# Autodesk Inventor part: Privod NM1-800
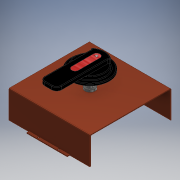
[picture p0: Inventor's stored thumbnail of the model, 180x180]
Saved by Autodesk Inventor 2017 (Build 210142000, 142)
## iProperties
Part Number: Privod NM1-800
Material: Типовые
Document SubType Name: Modeling
Designer: RSagdiev
Density: 1 g/cm^3
Appearance: По умолчанию
Author: RSagdiev
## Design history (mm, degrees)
sketch "Эскиз1"
  geometry: L1 (-52.5, 111.5)-(52.5, 111.5); L2 (52.5, 111.5)-(52.5, 103); L3 (52.5, 103)-(28.25, 103); L4 (-52.5, 103)-(-52.5, 111.5); L5 (0, 0)-(119.698, 0); L6 (0, 0)-(-104.809, 0); L7 (0, 94.88)-(0, -60.954); L8 (-28.25, 103)-(-24.25, 103); L9 (-24.25, 103)-(-24.25, 108); L10 (-26.25, 110)-(-26.25, 110); L11 (-28.25, 108)-(-28.25, 103); L12 (24.25, 103)-(24.25, 108); L13 (26.25, 110)-(26.25, 110); L14 (28.25, 103)-(24.25, 103); L15 (28.25, 108)-(28.25, 103); L16 (-28.25, 103)-(-52.5, 103); L17 (-24.25, 103)-(-28.25, 103); L18 (24.25, 103)-(-24.25, 103); L19 (28.25, 103)-(24.25, 103); A1 r 2 centre (-26.25, 108) between (-26.25, 110) and (-28.25, 108); A2 r 2 centre (-26.25, 108) between (-24.25, 108) and (-26.25, 110); A3 r 2 centre (26.25, 108) between (26.25, 110) and (24.25, 108); A4 r 2 centre (26.25, 108) between (28.25, 108) and (26.25, 110); 5 further points
  constraints: 38 end point, 10 point on line, 10 symmetric about line, 8 parallel, 8 point on circle, 4 centre point, 4 horizontal, 4 tangent, 2 perpendicular, 1 concentric, 1 midpoint, 1 vertical, 2 other
  dimensions: "d0" = 103 distance between parallel lines of L3 L6 (= 0.5 x Высота); "d1" = 8.5 distance of L1.end L2.end; "d2" = 105 distance between parallel lines of L2 L4 (= 0.5 x Ширина); "d3" = 4 distance of point (-28.25, 110) point (-24.25, 110); "d4" = 7 distance of point (-24.25, 110) L8.end; "d5" = 2 radius of A1 (derived); "d6" = 26.25 distance from line of L4 A1.centre (= 0.25 x d2)
extrude "Выдавливание1" new body sketch "Эскиз1" distance "d7" = 2; taper "d8" = 0 deg
mirror "Зеркальное отражение1"
sketch "Эскиз2"
  geometry: L1 (-52.5, 111.5)-(-52.5, 103) reference; L2 (52.5, 103)-(52.5, 111.5) reference; L3 (-52.5, -111.5)-(-52.5, -103) reference; L4 (52.5, -103)-(52.5, -111.5) reference; L5 (-105, 105)-(105, 105); L6 (105, 105)-(105, 103); L7 (105, 103)-(-105, 103); L8 (-105, 103)-(-105, 105); L9 (-52.5, 103)-(-28.25, 103) reference
  constraints: 8 end point, 2 parallel, 1 collinear, 1 horizontal, 1 perpendicular
  dimensions: "d13" = 210 distance of L5.start L5.end (= Ширина); "d14" = 2 distance of L5.end L6.end; "d15" = 52.5 distance between parallel lines of L1 L8 (= 0.25 x d13)
extrude "Выдавливание2" join sketch "Эскиз2" distance "d11" = 72 (computed from H1); taper "d12" = 0 deg
mirror "Зеркальное отражение2"
sketch "Эскиз3"
  geometry: L1 (-105, 105)-(-52.5, 105) reference; L2 (105, -105)-(-105, -105) reference; L3 (-105, 105)-(105, 105); L4 (105, 105)-(105, -105); L5 (105, -105)-(-105, -105); L6 (-105, -105)-(-105, 105); 1 further point
  constraints: 8 end point, 2 parallel, 1 horizontal, 1 perpendicular
extrude "Выдавливание3" join sketch "Эскиз3" distance "d16" = 2; taper "d17" = 0 deg
fillet "Сопряжение1" dims "d18" = 2
sketch "Эскиз4"
  geometry: L1 (105, -101)-(-105, -101) reference; L2 (105, -101)-(105, 101) reference; L3 (-105, 101)-(105, 101) reference; L4 (-105, 101)-(-105, -101) reference; L5 (-105, 101)-(-105, -101) reference; L6 (-105, -101)-(105, 101); L7 (105, -101)-(105, 101) reference; L8 (-105, 101)-(105, -101); C1 r 5 at (0, 0); 1 further point
  constraints: 4 end point, 1 centre point, 1 coincident
  dimensions: "d19" = 10 diameter of C1
extrude "Выдавливание4" cut sketch "Эскиз4" distance "d20" = 10; taper "d21" = 0 deg
sketch "Эскиз5"
  geometry: C1 r 5 at (0, 0) reference; C2 r 5 at (0, 0); C3 r 8 at (0, 0); 1 further point
  constraints: 2 centre point, 2 coincident
  dimensions: "d22" = 16 diameter of C3
extrude "Выдавливание5" new body sketch "Эскиз5" distance "d23" = 25.33333 (= 0.333333 x H1); taper "d24" = 0 deg
sketch "Эскиз6"
  geometry: C1 r 5 at (0, 0) reference; C2 r 5 at (0, 0); 1 further point
  constraints: 1 centre point, 1 coincident
extrude "Выдавливание6" new body sketch "Эскиз6" distance "d25" = 75.33333 (computed from H1); taper "d26" = 0 deg
sketch "Эскиз7"
  geometry: C1 r 5 at (0, 0) reference; C2 r 13 at (0, 0); C3 r 8 at (0, 0); C4 r 5 at (0, 0); 1 further point
  constraints: 3 centre point, 3 coincident
  dimensions: "d27" = 26 diameter of C2; "d28" = 16 diameter of C3; "d29" = 10 diameter of C4
extrude "Выдавливание7" new body sketch "Эскиз7" distance "d30" = 5; taper "d31" = 0 deg
extrude "Выдавливание8" join sketch "Эскиз7" distance "d32" = 20; taper "d33" = 0 deg
sketch "Эскиз8"
  geometry: C1 r 7 at (0, 0); 1 further point
  constraints: 1 centre point, 1 coincident
  dimensions: "d34" = 14 diameter of C1
extrude "Выдавливание9" new body sketch "Эскиз8" distance "d35" = 3; taper "d36" = 0 deg
fillet "Сопряжение2" dims "d37" = 3
sketch "Эскиз9"
  geometry: L1 (1, 13.17)-(-1, 13.17); L2 (-1, 13.17)-(-1, -13.17); L3 (-1, -13.17)-(1, -13.17); L4 (1, -13.17)-(1, 13.17); L5 (1, 13.17)-(-1, -13.17); L6 (-1, 13.17)-(1, -13.17); L7 (17.109, -1)-(-17.109, -1); L8 (-17.109, -1)-(-17.109, 1); L9 (-17.109, 1)-(17.109, 1); L10 (17.109, 1)-(17.109, -1); L11 (17.109, -1)-(-17.109, 1); L12 (-17.109, -1)-(17.109, 1); C1 r 4 at (0, 0) reference; C2 r 5 at (0, 0) reference; 1 further point
  constraints: 24 end point, 4 midpoint, 4 parallel, 2 horizontal, 2 perpendicular
  dimensions: "d38" = 2 distance of L3.end L2.end; "d39" = 2 distance of L7.end L8.end
extrude "Выдавливание10" cut sketch "Эскиз9" distance "d40" = 1; taper "d41" = 0 deg
sketch "Эскиз10"
  geometry: C1 r 17.5 at (0, 0); A1 r 4 centre (0, 0) between (1, -3.873) and (3.873, -1) reference; 1 further point
  constraints: 1 centre point, 1 coincident
  dimensions: "d42" = 35 diameter of C1
extrude "Выдавливание11" new body sketch "Эскиз10" distance "d43" = 6; taper "d44" = 0 deg; dims "d48" = 3, "d49" = 0
sketch "Эскиз11"
  geometry: C1 r 7 at (0, 0); C2 r 22.5 at (0, 0); 1 further point
  constraints: 2 centre point, 1 coincident
  dimensions: "d45" = 45 diameter of C2
extrude "Выдавливание12" join sketch "Эскиз11" distance "d46" = 6; taper "d47" = 0 deg
sketch "Эскиз12"
  geometry: L1 (-4, -49.361)-(4, -49.361); L2 (10, -43.361)-(10, 10.738); L3 (-10, 10.738)-(-10, -43.361); L4 (-10, -49.361)-(10, 14.361); L5 (10, -49.361)-(-10, 14.361); L6 (-12, 12.738)-(12, 12.738); A1 r 17.5 centre (0, 0) between (10, 14.361) and (0, -17.5) reference; A2 r 17.5 centre (0, 0) between (10, 14.361) and (0, -17.5) reference; A3 r 6 centre (-4, -43.361) between (-10, -43.361) and (-4, -49.361); A4 r 6 centre (4, -43.361) between (4, -49.361) and (10, -43.361); A5 r 2 centre (-12, 10.738) between (-10, 10.738) and (-12, 12.738); A6 r 2 centre (12, 10.738) between (12, 12.738) and (10, 10.738); A7 r 17.5 centre (0, 0) between (12, 12.738) and (-12, 12.738)
  constraints: 16 point on circle, 12 end point, 8 tangent, 6 point on line, 5 centre point, 2 equal radius, 2 horizontal, 2 midpoint, 1 coincident, 1 parallel, 1 perpendicular
  dimensions: "d63" = 20 distance of L4.end L5.end; "d64" = 6 radius of A3; "d66" = 10 distance from line of A1.centre L3; "d67" = 2 radius of A5; "d68" = 2 radius of A6 (derived)
extrude "Выдавливание13" join sketch "Эскиз12" distance "d55" = 10; taper "d56" = 0 deg
fillet "Сопряжение9" dims "d69" = 1
fillet "Сопряжение10" dims "d70" = 1
sketch "Эскиз13"
  geometry: L1 (0, 7.748)-(0, -17.5); L2 (-4, 7.748)-(-4, -17.5); L3 (4, -17.5)-(4, 7.748); A1 r 17.5 centre (0, 0) between (17.5, 0) and (0, -17.5) reference; A2 r 4 centre (0, 7.748) between (4, 7.748) and (-4, 7.748); A3 r 4 centre (0, -17.5) between (-4, -17.5) and (4, -17.5); 2 further points
  constraints: 8 end point, 5 point on circle, 4 tangent, 2 centre point, 1 midpoint, 1 parallel, 1 vertical
  dimensions: "d71" = 8 diameter of A3
extrude "Выдавливание14" cut sketch "Эскиз13" distance "d72" = 0.1; taper "d73" = 0 deg
sketch "Эскиз14"
  geometry: L1 (0, 9.652)-(1.649, 6.796); L2 (1.649, 6.796)-(-1.649, 6.796); L3 (-1.649, 6.796)-(0, 9.652); A1 r 4 centre (0, 7.748) between (4, 7.748) and (-4, 7.748) reference; 2 further points
  constraints: 6 end point, 1 coincident, 7 other
extrude "Выдавливание15" join sketch "Эскиз14" distance "d74" = 0.1; taper "d75" = 0 deg
node "Непосредственное редактирование1"
node "Твердое тело1"
node "Спроецированная петля1"
node "Твердое тело2"
node "Твердое тело3"
node "Твердое тело4"
node "Твердое тело5"
node "Спроецированная петля2"
node "Твердое тело6"
node "Спроецированная петля3"
feature "Масштаб1"
other parameters: "H1" = 76 [user parameter; used in 3 equation terms], "Высота" = 206 [user parameter; used in 1 equation term], "Ширина" = 210 [user parameter; used in 2 equation terms], "d76" = 22, "d77" = 22
